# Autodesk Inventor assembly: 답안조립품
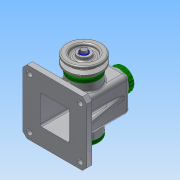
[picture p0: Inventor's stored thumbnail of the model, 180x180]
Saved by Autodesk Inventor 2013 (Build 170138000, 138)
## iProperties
Created: 2018-10
Part Number: 답안조립품
Document SubType Name: Assembly
Designer: Administrator
Author: Administrator
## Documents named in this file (14)
- C:\Users\Administrator\Desktop\481013V1005\답안조립품.iam
- C:\Users\Administrator\Desktop\481013V1005\본체.ipt
- C:\Users\Administrator\Desktop\481013V1005\V-벨트풀리.ipt
- C:\Users\Administrator\Desktop\481013V1005\뒤커버.ipt
- C:\Users\Administrator\Desktop\481013V1005\멈춤링 15 x 1.ipt
- C:\Users\Administrator\Desktop\481013V1005\베어링 15 x 35 x 11.ipt
- C:\Users\Administrator\Desktop\481013V1005\볼트 M4 x 10.ipt
- C:\Users\Administrator\Desktop\481013V1005\볼트 M6 x 12.ipt
- C:\Users\Administrator\Desktop\481013V1005\상부캡.ipt
- C:\Users\Administrator\Desktop\481013V1005\앞커버.ipt
- C:\Users\Administrator\Desktop\481013V1005\오일실 15 25 7.ipt
- C:\Users\Administrator\Desktop\481013V1005\와셔.ipt
- C:\Users\Administrator\Desktop\481013V1005\축.ipt
- C:\Users\Administrator\Desktop\481013V1005\키 5 x 5 x 14.ipt
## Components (1 placed, 1 different names)
1. V-벨트풀리:1
